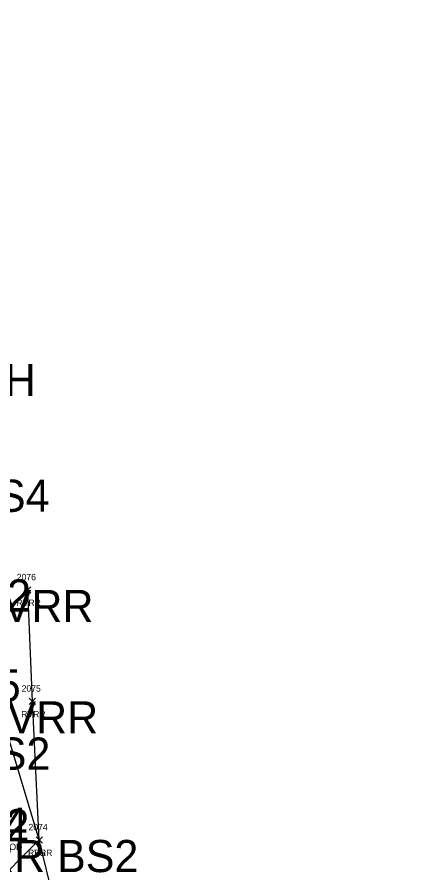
# Model space of a CAD drawing. Extents: x 1616840 to 1618410, y 488554 to 491945.
# Drawn here: x 1617557.1 to 1617683.6, y 490403.4 to 490669.5 of the extents above; entities that cross this region are included whole.
import ezdxf

# ---------------------------------------------------------------- set-up
doc = ezdxf.new("R2010")
doc.units = 0
for name, color, linetype in [('C_A', 7, 'Continuous'), ('C_I', 7, 'Continuous'), ('L_A', 7, 'Continuous'), ('L_C', 7, 'Continuous'), ('L_I', 7, 'Continuous'), ('L_TIC', 7, 'Continuous'), ('LAWE', 7, 'Continuous'), ('LELB', 7, 'Continuous')]:
    doc.layers.add(name, color=color, linetype=linetype)

msp = doc.modelspace()

# ---------------------------------------------------------------- linework, layer by layer
at = {"layer": 'L_TIC'}
for points in [[(1617559.38, 490490.36), (1617561.38, 490492.36)], [(1617561.38, 490490.36), (1617559.38, 490492.36)], [(1617560.84, 490455.72), (1617562.84, 490457.72)], [(1617562.84, 490455.72), (1617560.84, 490457.72)], [(1617562.97, 490412.61), (1617564.97, 490414.61)], [(1617564.97, 490412.61), (1617562.97, 490414.61)], [(1617562.97, 490412.61), (1617564.97, 490414.61)], [(1617564.97, 490412.61), (1617562.97, 490414.61)]]:
    msp.add_lwpolyline(points, dxfattribs=at)
at = {"layer": 'LAWE'}
msp.add_lwpolyline([(1617663.24, 489833.79), (1617654.8, 489852.96), (1617652.23, 489869.48), (1617656.92, 489898.41), (1617666.48, 489931.55), (1617678.36, 489965.64), (1617683.58, 490002.3), (1617678.91, 490029.8), (1617667.71, 490067.22), (1617651.98, 490099.5), (1617622.27, 490171.53), (1617610.13, 490206.58), (1617608.35, 490216.63), (1617602.61, 490254.67), (1617591.72, 490289.42), (1617582.26, 490325.24), (1617579.73, 490343.52), (1617580.31, 490345.5), (1617579.58, 490348.73), (1617579.24, 490350.23), (1617575.23, 490367.39), (1617563.97, 490413.61), (1617561.84, 490456.72), (1617560.38, 490491.36)], dxfattribs=at)
msp.add_lwpolyline([(1617663.24, 489833.79), (1617654.8, 489852.96), (1617652.23, 489869.48), (1617656.92, 489898.41), (1617666.48, 489931.55), (1617678.36, 489965.64), (1617683.58, 490002.3), (1617678.91, 490029.8), (1617667.71, 490067.22), (1617651.98, 490099.5), (1617622.27, 490171.53), (1617610.13, 490206.58), (1617608.35, 490216.63), (1617602.61, 490254.67), (1617591.72, 490289.42), (1617582.26, 490325.24), (1617579.73, 490343.52), (1617580.31, 490345.5), (1617579.58, 490348.73), (1617579.24, 490350.23), (1617575.23, 490367.39), (1617563.97, 490413.61), (1617561.84, 490456.72), (1617560.38, 490491.36)], dxfattribs=at)
at = {"layer": 'LELB'}
msp.add_lwpolyline([(1617553.07, 490349.28), (1617548.83, 490368.25), (1617548.72, 490398.45), (1617563.97, 490413.61), (1617554.43, 490445.46), (1617548.39, 490494.65), (1617543.6, 490525.66), (1617541.69, 490560.22), (1617532.07, 490597.35), (1617536.14, 490622.77), (1617537.09, 490669.51)], dxfattribs=at)
msp.add_lwpolyline([(1617553.07, 490349.28), (1617548.83, 490368.25), (1617548.72, 490398.45), (1617563.97, 490413.61), (1617554.43, 490445.46), (1617548.39, 490494.65), (1617543.6, 490525.66), (1617541.69, 490560.22), (1617532.07, 490597.35), (1617536.14, 490622.77), (1617537.09, 490669.51)], dxfattribs=at)

# ---------------------------------------------------------------- texts
at = {"layer": 'C_A'}
for s, p in [('SH', (1617544.31, 490551.65)), ('BS2 BS4', (1617512.89, 490515.66)), ('BS2', (1617536.11, 490484.65)), ('RVRR', (1617542.94, 490481.36)), ('RVRR', (1617544.4, 490446.72)), ('BS2', (1617542.15, 490435.46)), ('TS2', (1617536.39, 490413.19)), ('RVRR BS2', (1617527.9, 490403.61))]:
    msp.add_text(s, height=10, dxfattribs=at).set_placement(p)
at = {"layer": 'C_I'}
for s, p in [('2075', (1617528.45, 490456.72)), ('2074', (1617530.58, 490413.61))]:
    msp.add_text(s, height=10, dxfattribs=at).set_placement(p)
at = {"layer": 'L_A'}
for s, p in [('RVRR', (1617556.89, 490486.36)), ('RVRR', (1617558.35, 490451.72)), ('RVRR', (1617560.48, 490408.61)), ('BS', (1617562.41, 490408.61))]:
    msp.add_text(s, height=2, dxfattribs=at).set_placement(p)
at = {"layer": 'L_C'}
msp.add_text('L BASSWOOD', height=2, dxfattribs=at).set_placement((1617540.73, 490410.46))
at = {"layer": 'L_I'}
for s, p in [('2076', (1617556.99, 490494.36)), ('2075', (1617558.5, 490459.72)), ('2074', (1617560.63, 490416.61)), ('2074', (1617560.63, 490416.61))]:
    msp.add_text(s, height=2, dxfattribs=at).set_placement(p)

doc.saveas('drawing.dxf')
